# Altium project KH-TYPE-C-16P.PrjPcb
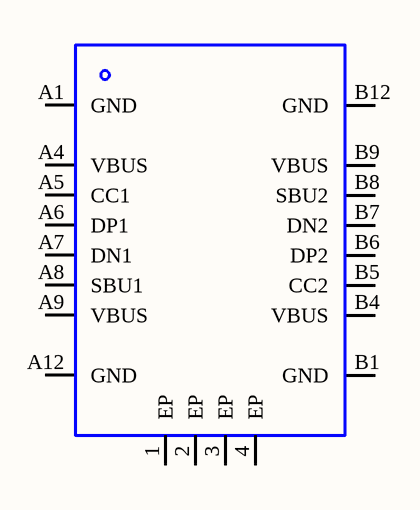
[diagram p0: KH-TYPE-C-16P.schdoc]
1 sheet, 1 parts. Net scope: global (net labels, ports and power ports of the same name join across sheets).

## Sheet KH-TYPE-C-16P.schdoc
size 127 x 101 mm

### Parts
USB?  kh-type-c-16p  [USB-C-SMD_KH-TYPE-C-16P]  (value not drawn)

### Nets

Not connected (* = marked no-connect by the designer): USB? 1(EP) 2(EP) 3(EP) 4(EP) A1(GND) A4(VBUS) A5(CC1) A6(DP1) A7(DN1) A8(SBU1) A9(VBUS) A12(GND) B1(GND) B4(VBUS) B5(CC2) B6(DP2) B7(DN2) B8(SBU2) B9(VBUS) B12(GND)

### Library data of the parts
USB? = kh-type-c-16p: 连接器类型:Type-C;协议标准:-;公母:母;安装方式:卧贴;触点数量:16P;端口数量:1;额定电流 - 电源:3A;工作温度:-40℃~+85℃;; Manufacturer: kinghelm(金航标); AddInBom: yes; ModelId: f2c381012fbf47e0b76dea5162270f01; ModelTransform: 351.9678,307.48,0,0,0,0,0,-45.276,-43.307; Connector Type: Type-C; Gender: 母; Number of Contacts: 16P; Number of Ports: 1; Current Rating-Power: 3A; Voltage Rating: 30V; Connect-Disconnect Life: 1万次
